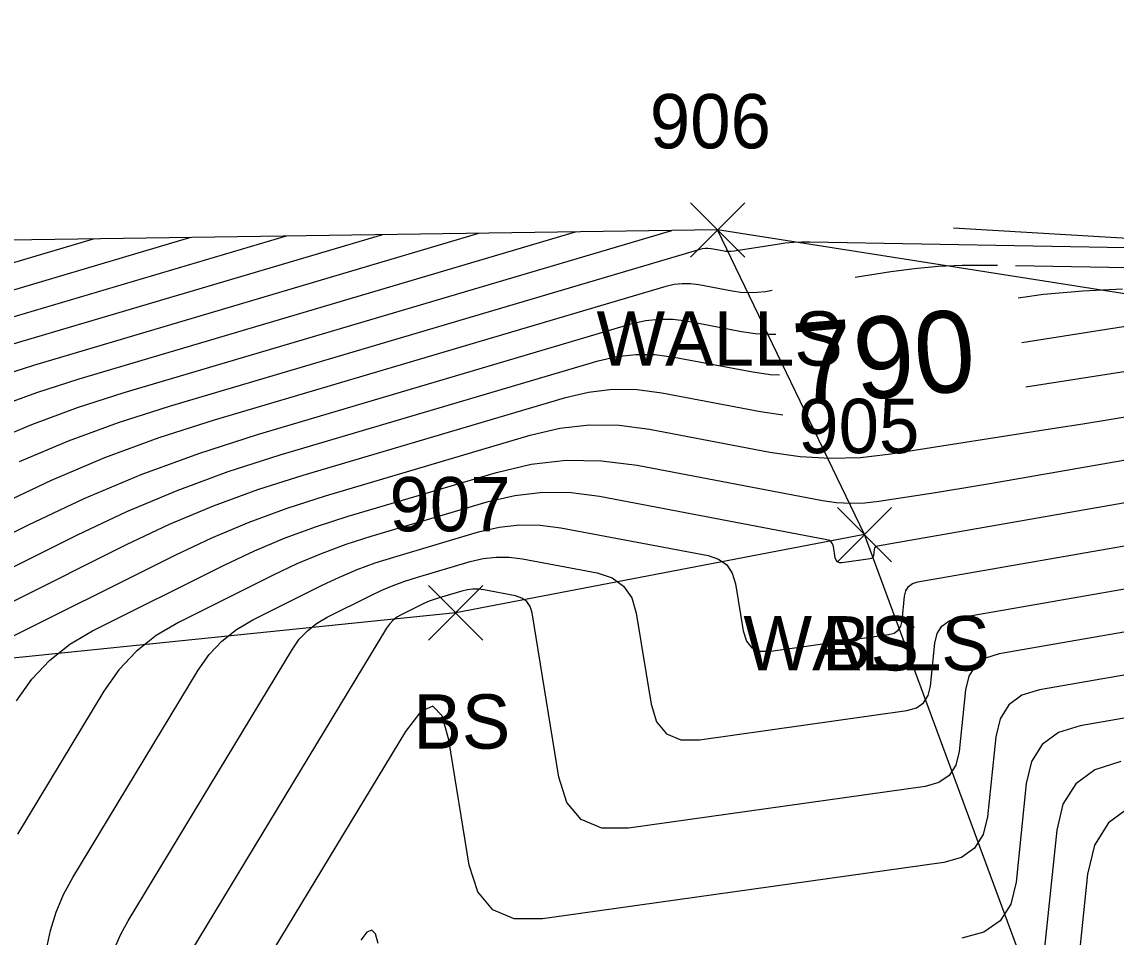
# Model space of a CAD drawing. Extents: x 1650836 to 1652450, y 332578 to 333908.
# Drawn here: x 1652115.54 to 1652155.83, y 332869.24 to 332902.93 of the extents above; entities that cross this region are included whole.
import ezdxf

# ---------------------------------------------------------------- set-up
doc = ezdxf.new("R2010")
doc.units = 0
for name, color, linetype in [('L_A', 7, 'Continuous'), ('L_I', 7, 'Continuous'), ('L_TIC', 7, 'Continuous'), ('LELB', 7, 'Continuous'), ('LSOGCMA', 7, 'Continuous'), ('LSOGCMA_T', 7, 'Continuous'), ('LSOGCMI', 7, 'Continuous'), ('LSOGP', 7, 'Continuous'), ('LWS', 7, 'Continuous')]:
    doc.layers.add(name, color=color, linetype=linetype)

msp = doc.modelspace()

# ---------------------------------------------------------------- linework, layer by layer
at = {"layer": 'L_TIC'}
for points in [[(1652140.158, 332894.272), (1652142.158, 332896.272)], [(1652142.158, 332894.272), (1652140.158, 332896.272)], [(1652145.567, 332883.053), (1652147.567, 332885.053)], [(1652147.567, 332883.053), (1652145.567, 332885.053)], [(1652145.567, 332883.053), (1652147.567, 332885.053)], [(1652147.567, 332883.053), (1652145.567, 332885.053)], [(1652130.516, 332880.175), (1652132.516, 332882.175)], [(1652132.516, 332880.175), (1652130.516, 332882.175)]]:
    msp.add_lwpolyline(points, dxfattribs=at)
at = {"layer": 'LELB'}
msp.add_lwpolyline([(1652146.567, 332884.053), (1652131.516, 332881.175), (1652103.316, 332878.294), (1652074.733, 332880.815), (1652057.387, 332879.464), (1652029.043, 332873.607), (1652021.327, 332871.103)], dxfattribs=at)
at = {"layer": 'LSOGCMA'}
for points in [[(1652091.323, 332883.761), (1652100.774, 332888.368), (1652101.483, 332888.714), (1652102.191, 332889.062), (1652102.898, 332889.412), (1652103.604, 332889.764), (1652106.428, 332891.173), (1652107.14, 332891.509), (1652107.865, 332891.814), (1652108.603, 332892.086), (1652109.353, 332892.326), (1652118.178, 332894.938)], [(1652152.363, 332891.131), (1652157.667, 332891.964)], [(1652107.245, 332878.882), (1652117.587, 332884.044), (1652119.405, 332884.902), (1652121.256, 332885.679), (1652123.138, 332886.373), (1652125.053, 332886.986), (1652136.758, 332890.45), (1652137.451, 332890.613), (1652138.148, 332890.69), (1652138.85, 332890.683), (1652139.556, 332890.591), (1652142.387, 332890.055), (1652143.095, 332889.951), (1652143.432, 332889.931)], [(1652156, 332875.697), (1652155.052, 332875.4), (1652154.343, 332874.88), (1652153.874, 332874.136), (1652153.643, 332873.17), (1652153.2, 332868.859), (1652152.969, 332867.897), (1652152.497, 332867.167), (1652151.785, 332866.668), (1652150.832, 332866.402), (1652129.106, 332863.345), (1652129.018, 332863.336), (1652128.93, 332863.332), (1652128.842, 332863.334), (1652128.754, 332863.341), (1652128.402, 332863.382), (1652128.332, 332863.382), (1652128.298, 332863.363), (1652128.301, 332863.324), (1652128.34, 332863.266), (1652132.629, 332858.188)]]:
    msp.add_lwpolyline(points, dxfattribs=at)
at = {"layer": 'LSOGCMI'}
for points in [[(1652125.275, 332895.041), (1652112.671, 332891.31), (1652111.599, 332890.968), (1652110.546, 332890.579), (1652109.511, 332890.145), (1652108.494, 332889.664), (1652104.461, 332887.652), (1652103.452, 332887.15), (1652102.442, 332886.65), (1652101.431, 332886.153), (1652100.419, 332885.658), (1652091.469, 332881.295)], [(1652092.351, 332882.993), (1652100.596, 332887.013), (1652101.457, 332887.433), (1652102.317, 332887.856), (1652103.175, 332888.281), (1652104.033, 332888.708), (1652107.461, 332890.419), (1652108.325, 332890.827), (1652109.206, 332891.196), (1652110.101, 332891.527), (1652111.012, 332891.818), (1652121.727, 332894.989)], [(1652114.252, 332887.415), (1652115.908, 332888.11), (1652117.593, 332888.732), (1652119.307, 332889.28), (1652139.47, 332895.248)], [(1652128.824, 332895.093), (1652114.33, 332890.803)], [(1652114.568, 332888.727), (1652116.095, 332889.291), (1652117.648, 332889.788), (1652135.921, 332895.196)], [(1652114.596, 332889.85), (1652115.989, 332890.295), (1652132.373, 332895.144)], [(1652149.84, 332895.35), (1652161.012, 332894.685)], [(1652161.006, 332894.53), (1652144.557, 332894.822), (1652144.254, 332894.821), (1652143.952, 332894.807), (1652143.651, 332894.779), (1652143.351, 332894.739), (1652141.763, 332894.489), (1652141.657, 332894.477), (1652141.552, 332894.475), (1652141.446, 332894.481), (1652141.341, 332894.496), (1652140.92, 332894.576), (1652140.815, 332894.59), (1652140.71, 332894.591), (1652140.607, 332894.579), (1652140.503, 332894.555), (1652120.966, 332888.772), (1652119.092, 332888.173), (1652117.249, 332887.493), (1652115.438, 332886.733)], [(1652151.461, 332893.956), (1652151.042, 332893.964), (1652150.16, 332893.96), (1652149.282, 332893.919), (1652148.406, 332893.839), (1652147.533, 332893.721), (1652146.221, 332893.515)], [(1652188.539, 332893.298), (1652152.126, 332893.945)], [(1652143.171, 332893.036), (1652142.918, 332892.996), (1652142.61, 332892.961), (1652142.303, 332892.953), (1652141.996, 332892.971), (1652141.69, 332893.016), (1652140.465, 332893.248), (1652140.16, 332893.287), (1652139.856, 332893.29), (1652139.555, 332893.257), (1652139.255, 332893.187), (1652122.625, 332888.265), (1652120.59, 332887.614), (1652118.589, 332886.876), (1652116.623, 332886.05), (1652114.691, 332885.138)], [(1652152.225, 332892.772), (1652153.161, 332892.899), (1652154.612, 332893.031), (1652156.067, 332893.1)], [(1652103.613, 332878.339), (1652115.786, 332884.415), (1652117.839, 332885.384), (1652119.929, 332886.261), (1652122.055, 332887.045), (1652124.217, 332887.737), (1652138.007, 332891.819), (1652138.503, 332891.935), (1652139.002, 332891.99), (1652139.505, 332891.985), (1652140.01, 332891.919), (1652142.038, 332891.535), (1652142.546, 332891.461), (1652143.054, 332891.431), (1652143.305, 332891.438)], [(1652160.365, 332890.713), (1652152.502, 332889.478)], [(1652143.556, 332888.454), (1652142.736, 332888.574), (1652139.101, 332889.263), (1652138.195, 332889.381), (1652137.294, 332889.39), (1652136.399, 332889.29), (1652135.51, 332889.082), (1652125.889, 332886.235), (1652124.221, 332885.701), (1652122.582, 332885.097), (1652120.971, 332884.421), (1652119.388, 332883.673), (1652110.877, 332879.425)], [(1652114.509, 332879.968), (1652121.189, 332883.302), (1652122.537, 332883.939), (1652123.909, 332884.514), (1652125.305, 332885.029), (1652126.725, 332885.483), (1652134.261, 332887.714), (1652135.347, 332887.968), (1652136.44, 332888.09), (1652137.54, 332888.078), (1652138.646, 332887.935), (1652143.084, 332887.094), (1652144.195, 332886.932), (1652145.307, 332886.866), (1652146.42, 332886.897), (1652147.535, 332887.024), (1652153.64, 332887.982), (1652154.605, 332888.136), (1652155.571, 332888.294), (1652156.535, 332888.456)], [(1652115.35, 332877.938), (1652115.908, 332878.733), (1652116.559, 332879.426), (1652117.304, 332880.019), (1652118.141, 332880.511), (1652122.991, 332882.931), (1652124.103, 332883.457), (1652125.236, 332883.932), (1652126.388, 332884.357), (1652127.56, 332884.732), (1652133.013, 332886.346), (1652134.296, 332886.646), (1652135.586, 332886.789), (1652136.885, 332886.776), (1652138.191, 332886.606), (1652145.018, 332885.313), (1652145.536, 332885.237), (1652146.056, 332885.206), (1652146.575, 332885.221), (1652147.096, 332885.28), (1652149.18, 332885.607), (1652149.7, 332885.69), (1652150.221, 332885.775), (1652150.741, 332885.863), (1652151.26, 332885.952), (1652161.472, 332887.731)], [(1652160.797, 332886.03), (1652147.04, 332883.634), (1652146.992, 332883.619), (1652146.957, 332883.593), (1652146.933, 332883.556), (1652146.922, 332883.507), (1652146.9, 332883.291), (1652146.888, 332883.243), (1652146.864, 332883.206), (1652146.829, 332883.181), (1652146.781, 332883.168), (1652145.736, 332883.021), (1652145.642, 332883.021), (1652145.57, 332883.051), (1652145.52, 332883.111), (1652145.492, 332883.2), (1652145.423, 332883.619), (1652145.395, 332883.713), (1652145.346, 332883.786), (1652145.274, 332883.837), (1652145.181, 332883.867), (1652136.81, 332885.454), (1652135.765, 332885.589), (1652134.727, 332885.6), (1652133.694, 332885.485), (1652132.668, 332885.245), (1652128.396, 332883.981), (1652127.472, 332883.685), (1652126.563, 332883.35), (1652125.669, 332882.975), (1652124.792, 332882.56), (1652121.312, 332880.824), (1652120.488, 332880.34), (1652119.755, 332879.756), (1652119.115, 332879.074), (1652118.565, 332878.292), (1652115.376, 332873.024)], [(1652116.452, 332868.792), (1652116.594, 332869.487), (1652116.802, 332870.159), (1652117.075, 332870.807), (1652117.413, 332871.431), (1652122.034, 332879.064), (1652122.436, 332879.637), (1652122.905, 332880.136), (1652123.442, 332880.564), (1652124.045, 332880.918), (1652126.593, 332882.189), (1652127.235, 332882.493), (1652127.889, 332882.767), (1652128.555, 332883.013), (1652129.232, 332883.229), (1652132.36, 332884.155), (1652133.111, 332884.331), (1652133.867, 332884.415), (1652134.627, 332884.407), (1652135.392, 332884.308), (1652140.808, 332883.282), (1652141.196, 332883.155), (1652141.493, 332882.941), (1652141.7, 332882.639), (1652141.816, 332882.248), (1652142.1, 332880.509), (1652142.217, 332880.137), (1652142.425, 332879.888), (1652142.725, 332879.763), (1652143.115, 332879.763), (1652147.456, 332880.373), (1652147.655, 332880.429), (1652147.803, 332880.533), (1652147.901, 332880.685), (1652147.95, 332880.886), (1652148.042, 332881.784), (1652148.09, 332881.986), (1652148.188, 332882.141), (1652148.336, 332882.249), (1652148.533, 332882.311), (1652160.364, 332884.372)], [(1652118.97, 332868.839), (1652119.184, 332869.349), (1652119.45, 332869.839), (1652125.503, 332879.836), (1652125.758, 332880.2), (1652126.055, 332880.517), (1652126.395, 332880.787), (1652126.778, 332881.012), (1652128.394, 332881.819), (1652128.801, 332882.011), (1652129.216, 332882.185), (1652129.638, 332882.341), (1652130.068, 332882.478), (1652132.051, 332883.065), (1652132.528, 332883.177), (1652133.007, 332883.23), (1652133.489, 332883.225), (1652133.975, 332883.162), (1652136.719, 332882.642), (1652137.274, 332882.461), (1652137.699, 332882.155), (1652137.995, 332881.722), (1652138.162, 332881.162), (1652138.709, 332877.818), (1652138.914, 332877.163), (1652139.28, 332876.725), (1652139.807, 332876.506), (1652140.494, 332876.505), (1652148.131, 332877.579), (1652148.481, 332877.677), (1652148.742, 332877.86), (1652148.915, 332878.127), (1652149, 332878.48), (1652149.162, 332880.061), (1652149.247, 332880.416), (1652149.419, 332880.689), (1652149.679, 332880.879), (1652150.027, 332880.988), (1652160.713, 332882.85)], [(1652161.062, 332881.328), (1652151.52, 332879.666), (1652151.022, 332879.51), (1652150.65, 332879.236), (1652150.403, 332878.846), (1652150.282, 332878.339), (1652150.05, 332876.075), (1652149.928, 332875.57), (1652149.681, 332875.186), (1652149.307, 332874.925), (1652148.806, 332874.785), (1652137.873, 332873.247), (1652136.89, 332873.248), (1652136.136, 332873.562), (1652135.612, 332874.189), (1652135.318, 332875.127), (1652134.329, 332881.17), (1652134.258, 332881.407), (1652134.133, 332881.59), (1652133.953, 332881.72), (1652133.718, 332881.796), (1652132.557, 332882.016), (1652132.351, 332882.043), (1652132.147, 332882.045), (1652131.944, 332882.022), (1652131.743, 332881.975), (1652130.903, 332881.727), (1652130.722, 332881.669), (1652130.543, 332881.603), (1652130.367, 332881.529), (1652130.195, 332881.448), (1652129.511, 332881.106), (1652129.349, 332881.011), (1652129.205, 332880.897), (1652129.079, 332880.762), (1652128.971, 332880.609), (1652121.487, 332868.247)], [(1652161.412, 332879.806), (1652153.013, 332878.343), (1652152.365, 332878.14), (1652151.881, 332877.784), (1652151.56, 332877.276), (1652151.403, 332876.616), (1652151.1, 332873.67), (1652150.942, 332873.012), (1652150.619, 332872.513), (1652150.133, 332872.173), (1652149.482, 332871.99), (1652134.706, 332869.912), (1652133.67, 332869.913), (1652132.877, 332870.244), (1652132.325, 332870.904), (1652132.015, 332871.892), (1652131.261, 332876.504), (1652131.02, 332877.388), (1652130.675, 332877.734), (1652130.226, 332877.541), (1652129.673, 332876.811), (1652123.524, 332866.654)], [(1652161.761, 332878.284), (1652154.506, 332877.02), (1652153.709, 332876.77), (1652153.112, 332876.332), (1652152.717, 332875.706), (1652152.523, 332874.893), (1652152.15, 332871.264), (1652151.955, 332870.455), (1652151.558, 332869.84), (1652150.959, 332869.42), (1652150.157, 332869.196)], [(1652156.333, 332874.026), (1652155.549, 332873.451), (1652155.03, 332872.628), (1652154.775, 332871.559), (1652154.25, 332866.454), (1652153.982, 332865.339), (1652153.436, 332864.494), (1652152.611, 332863.916), (1652151.508, 332863.607), (1652135.668, 332861.379), (1652135.317, 332861.341), (1652134.965, 332861.325), (1652134.613, 332861.332), (1652134.261, 332861.362), (1652132.851, 332861.524), (1652132.571, 332861.526), (1652132.437, 332861.45), (1652132.448, 332861.296), (1652132.604, 332861.064), (1652134.032, 332859.373)], [(1652128.656, 332869.002), (1652128.56, 332869.356), (1652128.422, 332869.494), (1652128.242, 332869.417), (1652128.021, 332869.125)]]:
    msp.add_lwpolyline(points, dxfattribs=at)
at = {"layer": 'LSOGP'}
msp.add_lwpolyline([(1652322.392, 332778.396), (1652286.244, 332816.269), (1652278.684, 332833.467), (1652279.741, 332838.109), (1652281.376, 332840.252), (1652284.715, 332848.326), (1652266.979, 332860.629), (1652252.966, 332867.026), (1652234.442, 332886.186), (1652219.944, 332895.981), (1652193.017, 332893.494), (1652163.094, 332891.822), (1652141.158, 332895.272), (1652101.604, 332894.697), (1652074.965, 332899.016), (1652042.229, 332910.088), (1652009.557, 332917.982), (1651992.258, 332920.35), (1651945.495, 332936.417)], dxfattribs=at)
at = {"layer": 'LWS'}
msp.add_lwpolyline([(1652157.84, 332853.547), (1652146.567, 332884.053), (1652141.158, 332895.272)], dxfattribs=at)

# ---------------------------------------------------------------- texts
at = {"layer": 'L_A'}
for s, p in [('WALLS', (1652136.701, 332890.272)), ('WALLS', (1652142.11, 332879.053)), ('BS', (1652145.008, 332879.053)), ('BS', (1652129.957, 332876.175))]:
    msp.add_text(s, height=2, dxfattribs=at).set_placement(p)
at = {"layer": 'L_I'}
for s, p in [('906', (1652138.662, 332898.272)), ('905', (1652144.126, 332887.053)), ('905', (1652144.126, 332887.053)), ('907', (1652129.076, 332884.175))]:
    msp.add_text(s, height=2, dxfattribs=at).set_placement(p)
at = {"layer": 'LSOGCMA_T'}
msp.add_text('790', height=3, rotation=4.8129, dxfattribs=at).set_placement((1652144.071, 332888.818))

doc.saveas('drawing.dxf')
